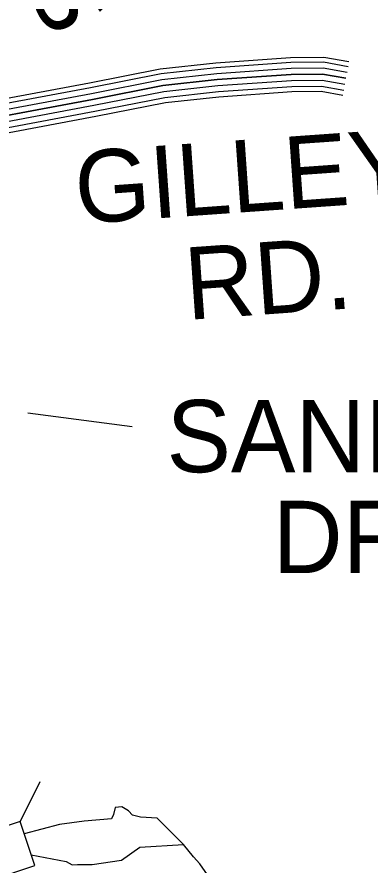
# Model space of a CAD drawing. Extents: x 1788175 to 1969470, y 584502 to 738744.
# Drawn here: x 1822217 to 1824024, y 703559 to 707900 of the extents above; entities that cross this region are included whole.
import ezdxf

# ---------------------------------------------------------------- set-up
doc = ezdxf.new("R2010")
doc.units = 0
for name, color, linetype in [('DESIGN - ROW - Right-of-Way and Easement Labels', 7, 'Continuous'), ('DESIGN - TRANSPORTATION - Edge of Traveled Way', 7, 'Continuous'), ('DESIGN - TRANSPORTATION - Text', 7, 'Continuous'), ('SURVEY - DRAINAGE - Storm Sewer', 7, 'Continuous'), ('SURVEY - TRANSPORTATION - Roads', 7, 'Continuous')]:
    doc.layers.add(name, color=color, linetype=linetype)

msp = doc.modelspace()

# ---------------------------------------------------------------- linework, layer by layer
at = {"layer": 'DESIGN - ROW - Right-of-Way and Easement Labels'}
msp.add_lwpolyline([(1822272.7, 705874.1), (1822806.8, 705803.5)], dxfattribs=at)
at = {"layer": 'DESIGN - TRANSPORTATION - Edge of Traveled Way'}
for points in [[(1823069.3, 703664.9), (1822934.1, 703799.8), (1822850.1, 703805), (1822808.2, 703813.6), (1822788.5, 703835.9), (1822754.8, 703856.4), (1822720.7, 703852.9), (1822712.2, 703817), (1822701.8, 703795.1), (1822561.6, 703783.1), (1822435.3, 703766.8), (1822254.1, 703719.5)], [(1822290.2, 703611.2), (1822469.7, 703577.2), (1822499.5, 703560.8), (1822526.7, 703562.1), (1822602.4, 703562.1), (1822751.9, 703583.3), (1822845.5, 703649.8), (1823069.3, 703664.9)]]:
    msp.add_lwpolyline(points, dxfattribs=at)
at = {"layer": 'DESIGN - TRANSPORTATION - Text'}
msp.add_lwpolyline([(1824034.8, 702741.9), (1823927.9, 702821.5), (1823865.2, 702908.5), (1823802.6, 703007.5), (1823752.5, 703132.4), (1823719.4, 703195), (1823659.9, 703233.9), (1823550.5, 703273.5), (1823418.7, 703295.3), (1823340.8, 703302.5), (1823291.4, 703347.2), (1823248.7, 703437.9), (1823191.8, 703508.8), (1823152.5, 703566.1), (1823120.6, 703602), (1823069.3, 703664.9)], dxfattribs=at)
at = {"layer": 'SURVEY - DRAINAGE - Storm Sewer'}
msp.add_line((1822334.9, 703985.1), (1822233.3, 703782), dxfattribs=at)
msp.add_lwpolyline([(1822007.9, 703706.8), (1822083, 703481.4), (1822308.4, 703556.6), (1822233.3, 703782)], close=True, dxfattribs=at)
at = {"layer": 'SURVEY - TRANSPORTATION - Roads'}
for points in [[(1821782.4, 707412.9), (1822588.4, 707563.6), (1822951, 707635.3), (1823234.9, 707666), (1823617.8, 707693), (1823788.7, 707694.9), (1823916.6, 707671.7)], [(1821786.9, 707388.6), (1822593.1, 707539.3), (1822954.7, 707610.8), (1823237.1, 707641.4), (1823618.8, 707668.3), (1823786.6, 707670.1), (1823912.2, 707647.4)], [(1821792.6, 707358.1), (1822598.9, 707508.9), (1822959.4, 707580.2), (1823239.9, 707610.5), (1823620, 707637.3), (1823784, 707639.1), (1823906.7, 707616.9)], [(1821798.3, 707327.6), (1822604.8, 707478.5), (1822964, 707549.5), (1823242.7, 707579.6), (1823621.3, 707606.3), (1823781.4, 707608.1), (1823901.1, 707586.4)], [(1823901.1, 707586.4), (1823781.4, 707608.1), (1823621.3, 707606.3), (1823242.7, 707579.6), (1822964, 707549.5), (1822604.8, 707478.5), (1821798.3, 707327.6)], [(1821798.3, 707327.6), (1822604.8, 707478.5), (1822964, 707549.5), (1823242.7, 707579.6), (1823621.3, 707606.3), (1823781.4, 707608.1), (1823901.1, 707586.4)], [(1821804, 707297.2), (1822610.6, 707448), (1822968.7, 707518.8), (1823245.4, 707548.7), (1823622.5, 707575.3), (1823778.8, 707577), (1823895.6, 707555.9)], [(1821809.7, 707266.7), (1822616.5, 707417.6), (1822973.4, 707488.1), (1823248.2, 707517.9), (1823623.8, 707544.3), (1823776.2, 707546), (1823890.1, 707525.3)], [(1821814.5, 707241.4), (1822621.3, 707392.3), (1822977.3, 707462.7), (1823250.5, 707492.2), (1823624.8, 707518.6), (1823774, 707520.3), (1823885.5, 707500)]]:
    msp.add_lwpolyline(points, dxfattribs=at)

# ---------------------------------------------------------------- texts
at = {"layer": 'DESIGN - ROW - Right-of-Way and Easement Labels'}
for s, rotation, p in [('BENDERS', 293.4398, (1821435.8, 709977.6)), ('GILLEY', 4.0337, (1822526.5, 706840.4)), ('RD.', 4.0337, (1823089.5, 706349.4))]:
    msp.add_text(s, height=370, rotation=rotation, dxfattribs=at).set_placement(p)
for s, p in [('SANFORD', (1822982.7, 705569.8)), ('DR.', (1823526.9, 705053.7))]:
    msp.add_text(s, height=370, dxfattribs=at).set_placement(p)

doc.saveas('drawing.dxf')
